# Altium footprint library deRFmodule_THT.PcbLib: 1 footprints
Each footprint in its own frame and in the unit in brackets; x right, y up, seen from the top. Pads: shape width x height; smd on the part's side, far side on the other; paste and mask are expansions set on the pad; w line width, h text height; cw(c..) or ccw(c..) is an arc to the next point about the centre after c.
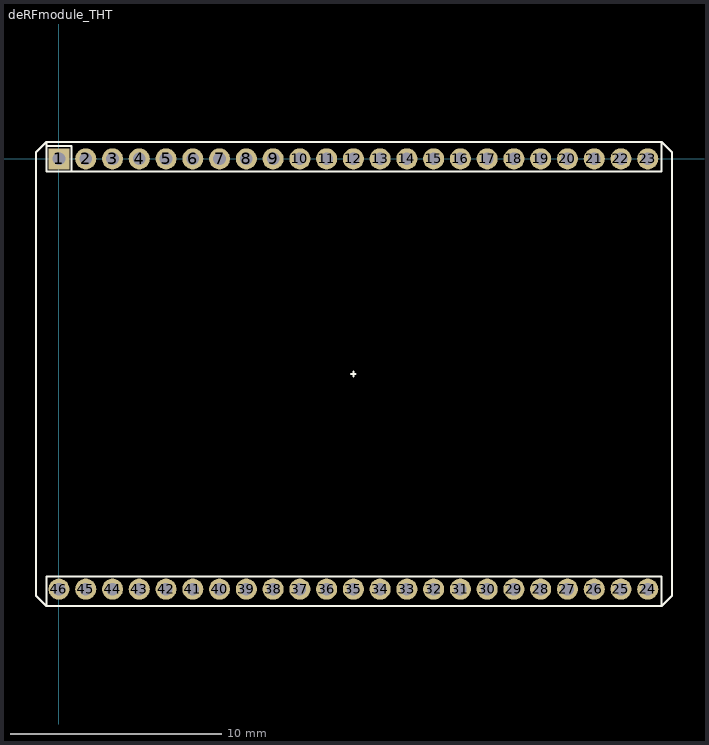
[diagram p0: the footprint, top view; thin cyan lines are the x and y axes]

## deRFmodule_THT [mm]
pads (46):
  rect 1x1 hole 0.6: 1(0,0)
  round 1 hole 0.6: 2(1.27,0) 3(2.54,0) 4(3.81,0) 5(5.08,0) 6(6.35,0) 7(7.62,0) 8(8.89,0) 9(10.16,0) 10(11.43,0) 11(12.7,0) 12(13.97,0) 13(15.24,0) 14(16.51,0) 15(17.78,0) 16(19.05,0) 17(20.32,0) 18(21.59,0) 19(22.86,0) 20(24.13,0) 21(25.4,0) 22(26.67,0) 23(27.94,0) 24(27.94,-20.425) 25(26.67,-20.425) 26(25.4,-20.425) 27(24.13,-20.425) 28(22.86,-20.425) 29(21.59,-20.425) 30(20.32,-20.425) 31(19.05,-20.425) 32(17.78,-20.425) 33(16.51,-20.425) 34(15.24,-20.425) 35(13.97,-20.425) 36(12.7,-20.425) 37(11.43,-20.425) 38(10.16,-20.425) 39(8.89,-20.425) 40(7.62,-20.425) 41(6.35,-20.425) 42(5.08,-20.425) 43(3.81,-20.425) 44(2.54,-20.425) 45(1.27,-20.425) 46(0,-20.425)
Top Overlay:
  lines w0.1: -0.575,0.6 0.6,0.6 0.6,-0.6 ; 13.87,-10.213 14.07,-10.213 ; 13.97,-10.338 13.97,-10.088 ; -0.6,-21.225 -0.6,-19.825 28.6,-19.825 28.6,-21.225 ; -0.6,-21.225 28.6,-21.225 ; -0.6,-21.225 -1.1,-20.725 -1.1,0.3 -0.6,0.8 ; -0.6,0.8 28.6,0.8 ; -0.6,0.8 -0.6,-0.6 28.6,-0.6 28.6,0.8 ; 28.6,-21.225 29.1,-20.725 29.1,0.3 28.6,0.8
